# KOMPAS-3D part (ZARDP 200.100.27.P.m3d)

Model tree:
1. Поверхность без истории:1
2. Поверхность без истории:2
3. Поверхность без истории:3
4. Поверхность без истории:4
5. Поверхность без истории:5
6. Поверхность без истории:6
7. Поверхность без истории:7
8. Поверхность без истории:8
9. Поверхность без истории:9
10. Поверхность без истории:10
11. Поверхность без истории:11
12. Поверхность без истории:12
13. Поверхность без истории:13
14. Поверхность без истории:14
15. Поверхность без истории:15
16. Поверхность без истории:16
17. Поверхность без истории:17
18. Поверхность без истории:18
19. Поверхность без истории:19
20. Поверхность без истории:20
21. Поверхность без истории:21
22. Поверхность без истории:22
23. Поверхность без истории:23
24. Поверхность без истории:24
25. Поверхность без истории:25
26. Поверхность без истории:26
27. Поверхность без истории:27
28. Поверхность без истории:28
29. Поверхность без истории:29
30. Поверхность без истории:30
31. Поверхность без истории:31
32. Поверхность без истории:32
33. Поверхность без истории:33
34. Поверхность без истории:34
35. Поверхность без истории:35
36. Поверхность без истории:36
37. Поверхность без истории:37
38. Поверхность без истории:38
39. Поверхность без истории:39
40. Поверхность без истории:40
41. Поверхность без истории:41
42. Поверхность без истории:42
43. Поверхность без истории:43
44. Поверхность без истории:44
45. Поверхность без истории:45
46. Поверхность без истории:46
47. Поверхность без истории:47
48. Поверхность без истории:48
49. Поверхность без истории:49
50. Поверхность без истории:50
51. Поверхность без истории:51
52. Поверхность без истории:52
53. Поверхность без истории:53
54. Поверхность без истории:54
55. Поверхность без истории:55
56. Поверхность без истории:56
57. Поверхность без истории:57
58. Поверхность без истории:58
59. Поверхность без истории:59
60. Поверхность без истории:60
61. Поверхность без истории:61
62. Поверхность без истории:62
63. Поверхность без истории:63
64. Поверхность без истории:64
65. Поверхность без истории:65
66. Поверхность без истории:66
67. Поверхность без истории:67
68. Поверхность без истории:68
69. Поверхность без истории:69
70. Поверхность без истории:70
71. Поверхность без истории:71
72. Поверхность без истории:72
73. Поверхность без истории:73
74. Поверхность без истории:74
75. Поверхность без истории:75
76. Поверхность без истории:76
77. Поверхность без истории:77
78. Поверхность без истории:78
79. Поверхность без истории:79
80. Поверхность без истории:80
81. Поверхность без истории:81
82. Поверхность без истории:82
83. Поверхность без истории:83
84. Поверхность без истории:84
85. Поверхность без истории:85
86. Поверхность без истории:86
87. Поверхность без истории:87
88. Поверхность без истории:88
89. Поверхность без истории:89
90. Поверхность без истории:90
91. Поверхность без истории:91
92. Поверхность без истории:92
93. Поверхность без истории:93
94. Поверхность без истории:94
95. Поверхность без истории:95
96. Поверхность без истории:96
97. Поверхность без истории:97
98. Поверхность без истории:98
99. Поверхность без истории:99
100. Поверхность без истории:100
101. Поверхность без истории:101
102. Поверхность без истории:102
103. Поверхность без истории:103
104. Поверхность без истории:104
105. Поверхность без истории:105
106. Поверхность без истории:106
107. Поверхность без истории:107
108. Поверхность без истории:108
109. Поверхность без истории:109
110. Поверхность без истории:110
111. Поверхность без истории:111
112. Поверхность без истории:112
113. Поверхность без истории:113
114. Поверхность без истории:114
115. Поверхность без истории:115
116. Поверхность без истории:116
117. Поверхность без истории:117
118. Поверхность без истории:118
119. Поверхность без истории:119
120. Поверхность без истории:120
121. Поверхность без истории:121
122. Поверхность без истории:122
123. Поверхность без истории:123
124. Поверхность без истории:124
125. Поверхность без истории:125
126. Поверхность без истории:126
127. Поверхность без истории:127
128. Поверхность без истории:128
129. Поверхность без истории:129
130. Поверхность без истории:130
131. Поверхность без истории:131
132. Поверхность без истории:132
133. Поверхность без истории:133
134. Поверхность без истории:134
135. Поверхность без истории:135
136. Поверхность без истории:136
137. Поверхность без истории:137
138. Поверхность без истории:138
139. Поверхность без истории:139
140. Поверхность без истории:140

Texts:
  ЗАРДП 200.100.27-ХХ.Р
